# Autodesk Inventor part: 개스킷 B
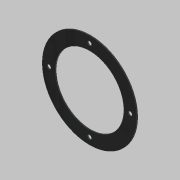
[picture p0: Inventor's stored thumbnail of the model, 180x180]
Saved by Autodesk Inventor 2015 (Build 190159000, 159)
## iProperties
Created: 2019-02
Part Number: 개스킷 B
Material: 고무
Document SubType Name: Modeling
Designer: mduedu
Density: 0.93 g/cm^3
Appearance: 고무 - 검은색 - 버전 1.1
Mass: 3.77481 g
Surface Area: 87.4305 cm^2
Volume: 4.05894 cm^3
Author: mduedu
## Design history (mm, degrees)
sketch "스케치1"
  geometry: C1 r 52.5 at (0, 0); C2 r 38 at (0, 0); 1 further point
  constraints: 2 centre point, 2 coincident
  dimensions: "d0" = 105 diameter of C1; "d1" = 76 diameter of C2
extrude "돌출1" new body sketch "스케치1" distance "d2" = 1; taper "d3" = 0 deg
sketch "스케치2" dims "d4" = 90
  geometry: 3 further points
  constraints: 2 vertical alignment, 1 coincident, 2 other
hole "구멍1" sketch "스케치2" at (0, 45) diameter "d5" = 4.5; stored, may be unused: countersink angle "d9" = 90 deg, drill point angle "d11" = 118 deg; dims "d6" = 6, "d7" = 4, "d8" = 2, "d10" = 8
node "솔리드1"
pattern_circular "원형 패턴1" dims angle "d13" = 360 deg
